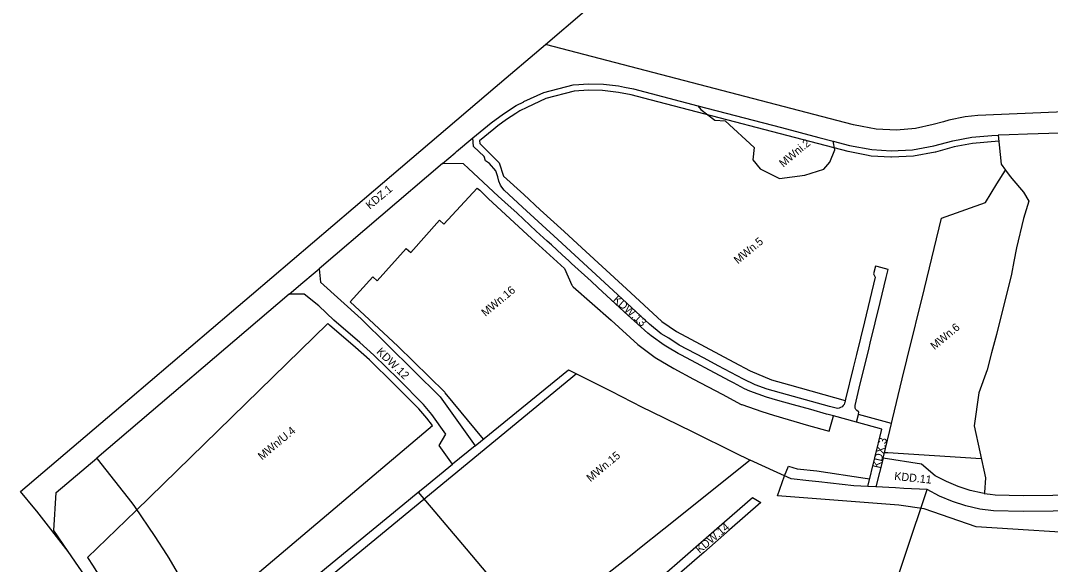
# Model space of a CAD drawing. Extents: x 7418616 to 7420822, y 5550745 to 5553106.
# Drawn here: x 7418910 to 7419553, y 5552185 to 5552525 of the extents above; entities that cross this region are included whole.
import ezdxf

# ---------------------------------------------------------------- set-up
doc = ezdxf.new("R2010")
doc.units = 0
for name, color, linetype in [('granica obszaru objętego planem', 7, 'Continuous'), ('linie rozgraniczające', 7, 'Continuous'), ('nieprzekraczalne linie zabudowy', 7, 'Continuous'), ('przeznaczenia terenów', 7, 'Continuous')]:
    doc.layers.add(name, color=color, linetype=linetype)

msp = doc.modelspace()

# ---------------------------------------------------------------- linework, layer by layer
at = {"layer": 'granica obszaru objętego planem'}
for points in [[(7418910.32, 5552230.55), (7418978.45, 5552288.63), (7419042.01, 5552342.81), (7419054.57, 5552353.51), (7419130.67, 5552418.38), (7419206.74, 5552483.23), (7419238.13, 5552509.99), (7419262.42, 5552530.7), (7419266.85, 5552534.47), (7419282.89, 5552548.15), (7419358.99, 5552613.02), (7419435.04, 5552677.85), (7419511.19, 5552742.76), (7419587.29, 5552807.63)], [(7418952.89, 5552174.15), (7418940.12, 5552192.95), (7418920.38, 5552218.17), (7418919.15, 5552219.68), (7418910.32, 5552230.55)]]:
    msp.add_lwpolyline(points, dxfattribs=at)
at = {"layer": 'linie rozgraniczające'}
for p, q in [((7419173.71, 5552435.53), (7419096.7, 5552369.76)), ((7419078, 5552353.8), (7418957.84, 5552251.35)), ((7419432.3, 5552273.8), (7419433.48, 5552278.66)), ((7419454.15, 5552272.98), (7419433.48, 5552278.66)), ((7419194.22, 5552259.04), (7419180.07, 5552247.51)), ((7419448.87, 5552251.34), (7419444.49, 5552233.34)), ((7419444.49, 5552233.34), (7419439.41, 5552233.6))]:
    msp.add_line(p, q, dxfattribs=at)
for points in [[(7418910.32, 5552230.55), (7418978.45, 5552288.63), (7419042.01, 5552342.81), (7419054.57, 5552353.51), (7419130.67, 5552418.38), (7419206.74, 5552483.23), (7419238.13, 5552509.99), (7419262.42, 5552530.7), (7419266.85, 5552534.47), (7419282.89, 5552548.15), (7419358.99, 5552613.02), (7419435.04, 5552677.85), (7419511.19, 5552742.76), (7419587.29, 5552807.63)], [(7419591.51, 5552469.04), (7419508.13, 5552465.61), (7419500.27, 5552464.62), (7419489.94, 5552462.53), (7419486.57, 5552461.58), (7419480.24, 5552459.85), (7419469.21, 5552457.42), (7419457.35, 5552456.4), (7419444.53, 5552456.99), (7419435.93, 5552458.55), (7419430.5, 5552459.61), (7419238.13, 5552509.99)], [(7419192.82, 5552451.55), (7419204.25, 5552461), (7419211.81, 5552466.66), (7419219.78, 5552471.71), (7419224.52, 5552474.12), (7419224.63, 5552474.18), (7419236.98, 5552479.95), (7419255.3, 5552484.62), (7419258.97, 5552484.89), (7419264.8, 5552485.31), (7419274.3, 5552485.12), (7419283.75, 5552484.03), (7419287.44, 5552483.29), (7419293.06, 5552482.16), (7419333.15, 5552471.66)], [(7419333.15, 5552471.66), (7419335.18, 5552469.19), (7419343.81, 5552462.57), (7419350.29, 5552462.15), (7419368.33, 5552445.5), (7419367.57, 5552437.74), (7419372.26, 5552432.11), (7419384.33, 5552426.11), (7419400.11, 5552428.31), (7419412, 5552431.92), (7419415.6, 5552436.36), (7419418.88, 5552443.97), (7419417.73, 5552449.5)], [(7419333.15, 5552471.66), (7419385.48, 5552457.95), (7419408.71, 5552451.87), (7419417.73, 5552449.5)], [(7419173.71, 5552435.53), (7419181.6, 5552442.27), (7419182.54, 5552443.05), (7419192.82, 5552451.55)], [(7419433.48, 5552278.66), (7419433.79, 5552280.21), (7419433.79, 5552280.27), (7419433.28, 5552280.5), (7419432.51, 5552281.06), (7419431.89, 5552281.8), (7419431.58, 5552282.53), (7419431.43, 5552283.17), (7419431.4, 5552283.69), (7419431.46, 5552284.23), (7419434.07, 5552295.06), (7419440.24, 5552320.31), (7419440.92, 5552323.19), (7419447.1, 5552348.53), (7419450.91, 5552364.31), (7419452.15, 5552369.28), (7419445.26, 5552371.08), (7419444.16, 5552371.39), (7419442.89, 5552366.56), (7419443.98, 5552364.38), (7419437.31, 5552336.62), (7419432.32, 5552316.17), (7419430.29, 5552307.76), (7419425.51, 5552288.23), (7419425.04, 5552286.18), (7419424.89, 5552285.75), (7419424.52, 5552284.93), (7419423.94, 5552284.18), (7419423.27, 5552283.49), (7419422.4, 5552282.94), (7419421.46, 5552282.57), (7419420.48, 5552282.46), (7419419.56, 5552282.49), (7419415.38, 5552283.69), (7419389.2, 5552290.95), (7419376.58, 5552294.53), (7419369.09, 5552297.22), (7419361.7, 5552300.74), (7419345.99, 5552308.98), (7419337.21, 5552313.85), (7419321.53, 5552322), (7419315.14, 5552326.32), (7419310.44, 5552328.98), (7419303.09, 5552335.13), (7419277.76, 5552358.67), (7419245.75, 5552388.1), (7419223.83, 5552408.3), (7419212.32, 5552418.79), (7419210.82, 5552420.7), (7419209.94, 5552422.04), (7419208.97, 5552424.38), (7419208.31, 5552427.17), (7419207.06, 5552430.95), (7419203.08, 5552435.57), (7419200.65, 5552437.26), (7419199.77, 5552439.88), (7419193.22, 5552446.11), (7419192.82, 5552451.55)], [(7419417.73, 5552449.5), (7419427.96, 5552446.82), (7419441.9, 5552444.18), (7419453.94, 5552443.38), (7419467.36, 5552444.07), (7419480.67, 5552446.46), (7419492.48, 5552449.76), (7419504.29, 5552452.07), (7419516.82, 5552453.1), (7419520.77, 5552453.24)], [(7419637.2, 5552429.07), (7419637.23, 5552434.4), (7419624.8, 5552436.75), (7419620.16, 5552451.72), (7419575.16, 5552454.94), (7419572.63, 5552454.93), (7419539.06, 5552453.86), (7419527.6, 5552453.48), (7419520.77, 5552453.24)], [(7419520.77, 5552453.24), (7419522.59, 5552435.07), (7419525.33, 5552431.4)], [(7419432.3, 5552273.8), (7419418.03, 5552277.72), (7419414.65, 5552278.55), (7419413.66, 5552278.87), (7419403.85, 5552281.65), (7419392.9, 5552284.71), (7419383.23, 5552287.43), (7419376.08, 5552289.46), (7419365.68, 5552293.28), (7419362.45, 5552294.71), (7419355.42, 5552298.44), (7419352.95, 5552299.73), (7419344.02, 5552304.55), (7419337.33, 5552308.06), (7419335.15, 5552309.26), (7419323.1, 5552315.65), (7419320.92, 5552316.85), (7419314.27, 5552320.64), (7419312.13, 5552321.99), (7419303.99, 5552327.79), (7419302.08, 5552329.37), (7419295.52, 5552335.23), (7419287.29, 5552342.78), (7419270.83, 5552357.99), (7419266.59, 5552361.89), (7419254.32, 5552373.03), (7419252.58, 5552374.63), (7419248.5, 5552378.39), (7419241.83, 5552384.65), (7419239.12, 5552387.02), (7419232.29, 5552393.3), (7419220.39, 5552404.38), (7419212.78, 5552411.27), (7419208.58, 5552415.12), (7419189.98, 5552432.38), (7419186.85, 5552435.35), (7419173.71, 5552435.53)], [(7419454.15, 5552272.98), (7419454.83, 5552275.79), (7419460.92, 5552300.83), (7419463.83, 5552312.77), (7419474.7, 5552357.46), (7419485.38, 5552401.35), (7419512.9, 5552411.08), (7419520.01, 5552422.72), (7419525.33, 5552431.4)], [(7419525.33, 5552431.4), (7419527.65, 5552428.3), (7419529.3, 5552426.16), (7419536.54, 5552417.67), (7419539.88, 5552411.9), (7419536.58, 5552401.22), (7419532.21, 5552382.88), (7419530.54, 5552374.19), (7419529.05, 5552366.33), (7419519.67, 5552328.6), (7419516.67, 5552317.13), (7419513.89, 5552306.62), (7419508.72, 5552292.18), (7419505.77, 5552271.49), (7419512.84, 5552239.05), (7419512.32, 5552229.85), (7419512.1, 5552229.24)], [(7419078, 5552353.8), (7419086.48, 5552361.03), (7419092.95, 5552366.56), (7419096.7, 5552369.76)], [(7419096.7, 5552369.76), (7419097.59, 5552361.32), (7419122.97, 5552338.34), (7419172.36, 5552289.75), (7419194.22, 5552259.04)], [(7419180.07, 5552247.51), (7419171.72, 5552259.32), (7419175.87, 5552266.42), (7419167.22, 5552278.69), (7419161.97, 5552284.94), (7419146.23, 5552300.6), (7419130.88, 5552315.72), (7419122.08, 5552323.59), (7419105.88, 5552337.56), (7419096.62, 5552346.51), (7419087.3, 5552353.84), (7419078, 5552353.8)], [(7419194.22, 5552259.04), (7419252.53, 5552306.54), (7419279.06, 5552293.11), (7419298.43, 5552283.29), (7419304.07, 5552280.52), (7419330.08, 5552267.71), (7419356.1, 5552254.9), (7419365.97, 5552250.04)], [(7419439.41, 5552233.6), (7419448.14, 5552269.44), (7419432.3, 5552273.8)], [(7419448.87, 5552251.34), (7419453.07, 5552268.56), (7419454.15, 5552272.98)], [(7418940.12, 5552192.95), (7418931.08, 5552206.09), (7418932.57, 5552229.8), (7418957.84, 5552251.35)], [(7418957.84, 5552251.35), (7418958.23, 5552250.88), (7418979.79, 5552223.39), (7418981.48, 5552221.04), (7418994.25, 5552202.25), (7419001.5, 5552191.05), (7419002.87, 5552188.82), (7419008.04, 5552179.82), (7419008.95, 5552178.16), (7419017.08, 5552162.68), (7419017.65, 5552161.54), (7419018.66, 5552159.37), (7419027.36, 5552139.38), (7419032.89, 5552126.63)], [(7419481.42, 5552240.33), (7419472.99, 5552247.66), (7419448.87, 5552251.34)], [(7419158.66, 5552230.06), (7419161.41, 5552232.32), (7419180.07, 5552247.51)], [(7419365.97, 5552250.04), (7419312.1, 5552206.93), (7419296.89, 5552194.85), (7419293.29, 5552192.01), (7419273.97, 5552176.76), (7419270.76, 5552174.26), (7419254.96, 5552161.91), (7419239.68, 5552149.67), (7419236.93, 5552147.47)], [(7419439.41, 5552233.6), (7419430.6, 5552234.06), (7419408.77, 5552236.46), (7419402.58, 5552237.14), (7419391.47, 5552238.36), (7419382.74, 5552242.36), (7419365.97, 5552250.04)], [(7419512.1, 5552229.24), (7419511.07, 5552229.38), (7419503.33, 5552231.15), (7419495.77, 5552233.57), (7419488.45, 5552236.64), (7419481.42, 5552240.33)], [(7419512.1, 5552229.24), (7419515.84, 5552228.71), (7419518.93, 5552228.31), (7419536.47, 5552227.92), (7419554.92, 5552228.27), (7419584.16, 5552228.89), (7419586.94, 5552229.19), (7419599.4, 5552241.21)], [(7419471.68, 5552024.34), (7419469.73, 5552025.85), (7419467.37, 5552027.79), (7419459.79, 5552030.67), (7419456.81, 5552032.24), (7419455.37, 5552033), (7419450.17, 5552038.3), (7419443.52, 5552045.43), (7419436.66, 5552053.6), (7419433.69, 5552062.45), (7419422.76, 5552071.31), (7419476.4, 5552231.68)], [(7419476.4, 5552231.68), (7419461.91, 5552232.43), (7419456.73, 5552232.7), (7419444.49, 5552233.34)], [(7419594.63, 5552220.26), (7419589.63, 5552219.42), (7419584.8, 5552218.9), (7419555.13, 5552218.27), (7419536.45, 5552217.92), (7419517.97, 5552218.33), (7419509.26, 5552219.54), (7419500.68, 5552221.5), (7419492.31, 5552224.19), (7419484.19, 5552227.59), (7419476.4, 5552231.68)], [(7418952.89, 5552174.15), (7418940.12, 5552192.95), (7418920.38, 5552218.17), (7418919.15, 5552219.68), (7418910.32, 5552230.55)], [(7419047.97, 5552139.03), (7419112.04, 5552191.72), (7419149.11, 5552222.2), (7419158.66, 5552230.06)], [(7419158.66, 5552230.06), (7419188.56, 5552194.58), (7419214.09, 5552164.29), (7419227.12, 5552148.84)], [(7419298.49, 5552165.33), (7419299.92, 5552167.9), (7419308.97, 5552175.78), (7419327.07, 5552191.53), (7419345.17, 5552207.3), (7419367.41, 5552226.67), (7419372.62, 5552223.69), (7419353.06, 5552206.57), (7419336.88, 5552192.4), (7419334.25, 5552190.1), (7419318.45, 5552176.27), (7419305.31, 5552164.76), (7419303.22, 5552160.41)]]:
    msp.add_lwpolyline(points, dxfattribs=at)
at = {"layer": 'nieprzekraczalne linie zabudowy'}
for points in [[(7419521.14, 5552449.53), (7419504.84, 5552448.1), (7419493.4, 5552445.87), (7419481.75, 5552442.61), (7419481.38, 5552442.52), (7419467.88, 5552440.1), (7419454.15, 5552439.39), (7419453.67, 5552439.39), (7419441.56, 5552440.2), (7419438.56, 5552440.74), (7419427.08, 5552442.92), (7419299.52, 5552476.33), (7419291.64, 5552478.36), (7419283.59, 5552479.98), (7419278.64, 5552480.59), (7419273.75, 5552481.13), (7419264.91, 5552481.31), (7419255.94, 5552480.66), (7419238.33, 5552476.17), (7419226.39, 5552470.58), (7419222.15, 5552468.43), (7419219.61, 5552466.87), (7419213.65, 5552463.04), (7419208.31, 5552459.04), (7419205.76, 5552457.06), (7419196.96, 5552449.78), (7419197.09, 5552447.94), (7419209.11, 5552435.92), (7419211.87, 5552427.62), (7419224.48, 5552416.19), (7419234.73, 5552406.65), (7419249.77, 5552392.98), (7419260.83, 5552382.72), (7419288.79, 5552357.16), (7419310.81, 5552336.84), (7419319.97, 5552330.49), (7419355.7, 5552311.43), (7419365.95, 5552305.86), (7419379.28, 5552300.36), (7419390.47, 5552297.26), (7419425.31, 5552287.35)], [(7419199.35, 5552263.22), (7419175.53, 5552292.18), (7419175.16, 5552292.6), (7419145.99, 5552321.3), (7419116.14, 5552349.12), (7419130.37, 5552364.66), (7419133.04, 5552362.2), (7419151.19, 5552382.47), (7419153.95, 5552379.93), (7419171.97, 5552400.02), (7419174.54, 5552397.67), (7419195.43, 5552420.15), (7419197.03, 5552418.76), (7419202.51, 5552413.43), (7419229.33, 5552388.62), (7419249.91, 5552369.8), (7419254.58, 5552359.43), (7419254.7, 5552359.2), (7419254.99, 5552358.76), (7419255.34, 5552358.37), (7419279.01, 5552337.53), (7419295.84, 5552322.31), (7419306.6, 5552314.18), (7419318.32, 5552307.28), (7419330.55, 5552300.76), (7419348.41, 5552291.38), (7419360.33, 5552284.96), (7419360.77, 5552284.78), (7419373.12, 5552280.42), (7419380.43, 5552278.26), (7419402.25, 5552271.71), (7419415.29, 5552268.12), (7419417.31, 5552275.4), (7419417.94, 5552277.74)], [(7418952.04, 5552189.16), (7418955.55, 5552183.91), (7418959.46, 5552177.78), (7418963.26, 5552171.4), (7418974.37, 5552151.34), (7418976.69, 5552146.79), (7418984.13, 5552130.89), (7418988.57, 5552120.49), (7419023, 5552149.4), (7419167.49, 5552271.78), (7419164.04, 5552276.25), (7419159.02, 5552282.23), (7419143.41, 5552297.76), (7419128.14, 5552312.81), (7419119.44, 5552320.59), (7419103.24, 5552334.55), (7419102.21, 5552335.54), (7418982.36, 5552218.45), (7418952.04, 5552189.16)], [(7419257.49, 5552304.03), (7419001.12, 5552092.71), (7419008.7, 5552075.95), (7419018.24, 5552055.41), (7419033.59, 5552020.49), (7419042.77, 5552000), (7419106.81, 5552050.65), (7419106.93, 5552050.97), (7419107.06, 5552051.2), (7419107.22, 5552051.41), (7419107.48, 5552051.65), (7419133.28, 5552072.17), (7419142.2, 5552079.3), (7419164.04, 5552096.68), (7419178.61, 5552108.18), (7419192.13, 5552118.99), (7419197.3, 5552123.02), (7419224.3, 5552144.42)], [(7419449.73, 5552254.85), (7419451.86, 5552254.79), (7419510.21, 5552251.14)], [(7419585.47, 5552203.41), (7419507.07, 5552208.43), (7419474.66, 5552219.63), (7419458.66, 5552222.01), (7419382.96, 5552227.74), (7419387.28, 5552240.28), (7419389.79, 5552246.41), (7419395.19, 5552244.75), (7419407.61, 5552243.39), (7419437.81, 5552238.92), (7419440.6, 5552238.48)]]:
    msp.add_lwpolyline(points, dxfattribs=at)

# ---------------------------------------------------------------- texts
at = {"layer": 'przeznaczenia terenów'}
for s, rotation, p in [('MWni.2', 39.84394, (7419386.56, 5552432.94)), ('KDZ.1', 39.84394, (7419128.42, 5552406.61)), ('MWn.5', 39.84394, (7419358.29, 5552372.43)), ('MWn.16', 39.84394, (7419200.62, 5552339.61)), ('KDW.13', 318.12058, (7419279.9, 5552349.88)), ('MWn.6', 39.84394, (7419481.04, 5552318.79)), ('KDW.12', 315.96, (7419132.2, 5552317.38)), ('MWn/U.4', 39.84394, (7419061.07, 5552249.86)), ('KDX.3', 76.80981, (7419447.03, 5552244.65)), ('MWn.15', 39.84394, (7419266.21, 5552236.23)), ('KDD.11', 353.99285, (7419455.73, 5552237.79)), ('KDW.14', 39.84394, (7419334.36, 5552191.56))]:
    msp.add_text(s, height=5, rotation=rotation, dxfattribs=at).set_placement(p)

doc.saveas('drawing.dxf')
